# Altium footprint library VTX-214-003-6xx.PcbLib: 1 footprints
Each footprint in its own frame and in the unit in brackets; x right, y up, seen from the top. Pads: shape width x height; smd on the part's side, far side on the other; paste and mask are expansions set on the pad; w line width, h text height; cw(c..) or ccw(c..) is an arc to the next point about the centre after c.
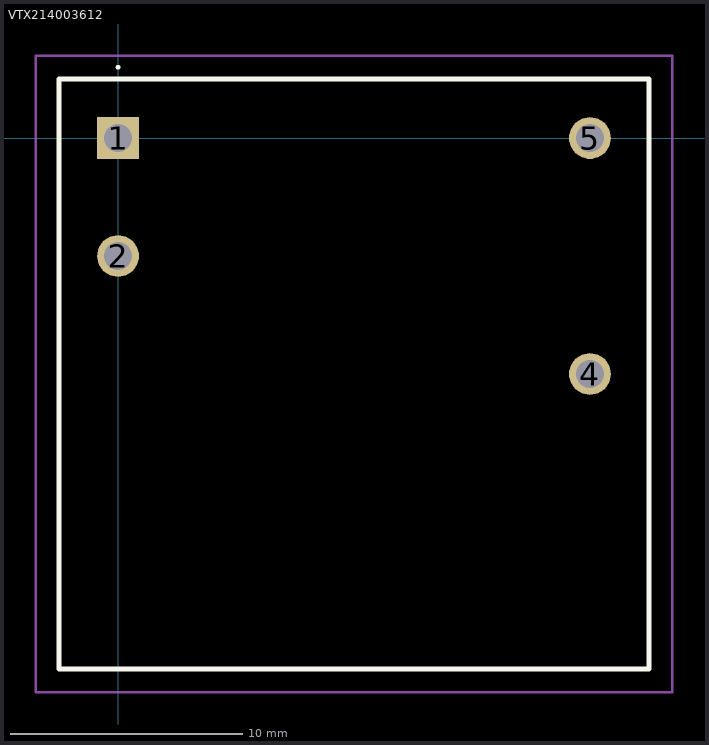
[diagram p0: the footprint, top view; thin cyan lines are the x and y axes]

## VTX214003612 [mm]
pads (4):
  rect 1.8x1.8 hole 1.2: 1(0,0)
  round 1.8 hole 1.2: 2(0,-5.08) 4(20.32,-10.16) 5(20.32,0)
Top Overlay:
  lines w0.1: 0,3 0,3 ; 0,3 ccw(c0,3.05) 0,3.1 ; 0,3 cw(c0,3.05) 0,3.1 ; 0,3.1 0,3.1
  lines w0.2: -2.54,-22.86 22.86,-22.86 22.86,2.54 -2.54,2.54 -2.54,-22.86
Mechanical 15:
  lines w0.1: -2.54,-22.86 22.86,-22.86 22.86,2.54 -2.54,2.54 -2.54,-22.86
Mechanical 20:
  lines w0.1: -3.54,-23.86 23.86,-23.86 23.86,3.54 -3.54,3.54 -3.54,-23.86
